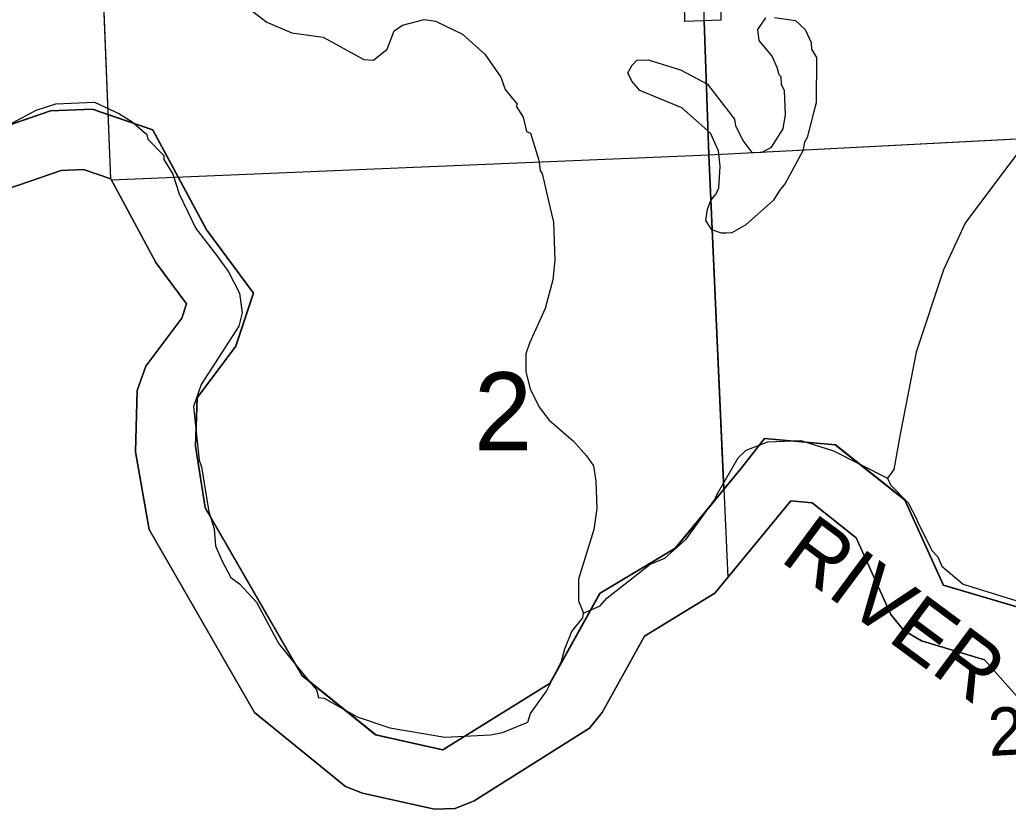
# Model space of a CAD drawing. Extents: x 128.7 to 185.5, y -21.4 to 12.6.
# Drawn here: x 156.23 to 157.877, y -14.035 to -12.718 of the extents above; entities that cross this region are included whole.
import ezdxf

# ---------------------------------------------------------------- set-up
doc = ezdxf.new("R2010")
doc.units = 0
for name, color, linetype in [('tdCoClipBndry', 7, 'Continuous'), ('tdCoCoBndry', 7, 'Continuous'), ('tdCoCoBndryPart', 7, 'Continuous'), ('tdCoHydroRiver', 7, 'Continuous'), ('tdCoHydroTxtLg', 7, 'Continuous'), ('tdCoSecRdTxt', 7, 'Continuous'), ('tdCoSecRteBand', 7, 'Continuous'), ('tdCoSectLine', 7, 'Continuous'), ('tdCoSectLinePart', 7, 'Continuous'), ('tdCoSectNmbr', 7, 'Continuous'), ('tdCoTwpBndry', 7, 'Continuous'), ('tdCoTwpBndryShd', 7, 'Continuous')]:
    doc.layers.add(name, color=color, linetype=linetype)

msp = doc.modelspace()

# ---------------------------------------------------------------- linework, layer by layer
at = {"layer": 'tdCoClipBndry'}
msp.add_lwpolyline([(157.9214, -13.8795), (157.8377, -13.7853), (157.7328, -13.754), (157.7035, -13.7363), (157.682, -13.7098), (157.6237, -13.5818), (157.5505, -13.5239), (157.5151, -13.5206), (157.3885, -13.6745), (157.2711, -13.7462), (157.2008, -13.873), (157.1797, -13.8993), (156.9873, -14.0205), (156.9554, -14.0333), (156.9211, -14.0346), (156.8011, -14.0079), (156.773, -13.9969), (156.6213, -13.8731), (156.4455, -13.5681), (156.4229, -13.4385), (156.4259, -13.3366), (156.4402, -13.2958), (156.5, -13.2156), (156.5079, -13.1918), (156.457, -13.1228), (156.3818, -12.9837), (156.336, -12.9681), (156.2993, -12.9695), (156.0482, -13.0555)], dxfattribs=at)
at = {"layer": 'tdCoCoBndry'}
for p, q in [((156.2812, -12.8702), (155.999, -12.9668)), ((155.999, -12.9668), (156.2812, -12.8702)), ((156.351, -12.8675), (156.2812, -12.8702)), ((156.2812, -12.8702), (156.351, -12.8675)), ((156.4516, -12.9018), (156.351, -12.8675)), ((156.351, -12.8675), (156.4516, -12.9018)), ((156.5417, -13.0692), (156.4516, -12.9018)), ((156.4516, -12.9018), (156.5417, -13.0692)), ((156.6196, -13.174), (156.5417, -13.0692)), ((156.5417, -13.0692), (156.6196, -13.174)), ((156.59, -13.2627), (156.6196, -13.174)), ((156.6196, -13.174), (156.59, -13.2627)), ((156.5255, -13.3486), (156.59, -13.2627)), ((156.59, -13.2627), (156.5255, -13.3486)), ((156.5228, -13.4292), (156.5255, -13.3486)), ((156.5255, -13.3486), (156.5228, -13.4292)), ((157.4714, -13.4162), (157.4337, -13.4646)), ((157.4337, -13.4646), (157.4714, -13.4162)), ((157.5896, -13.427), (157.4714, -13.4162)), ((157.4714, -13.4162), (157.5896, -13.427)), ((156.5388, -13.5314), (156.5228, -13.4292)), ((156.5228, -13.4292), (156.5388, -13.5314)), ((157.7051, -13.5185), (157.5896, -13.427)), ((157.5896, -13.427), (157.7051, -13.5185)), ((157.4337, -13.4646), (157.3235, -13.5989)), ((157.3235, -13.5989), (157.4337, -13.4646)), ((157.7695, -13.6609), (157.7051, -13.5185)), ((157.7051, -13.5185), (157.7695, -13.6609)), ((156.6999, -13.8109), (156.5388, -13.5314)), ((156.5388, -13.5314), (156.6999, -13.8109)), ((157.3235, -13.5989), (157.1972, -13.6741)), ((157.1972, -13.6741), (157.3235, -13.5989)), ((157.8938, -13.6975), (157.7695, -13.6609)), ((157.7695, -13.6609), (157.8938, -13.6975)), ((157.1972, -13.6741), (157.1138, -13.8245)), ((157.1138, -13.8245), (157.1972, -13.6741)), ((156.8235, -13.9104), (156.6999, -13.8109)), ((156.6999, -13.8109), (156.8235, -13.9104)), ((157.1138, -13.8245), (156.935, -13.9355)), ((156.935, -13.9355), (157.1138, -13.8245)), ((156.935, -13.9355), (156.8235, -13.9104)), ((156.8235, -13.9104), (156.935, -13.9355))]:
    msp.add_line(p, q, dxfattribs=at)
for points in [[(155.9986, -12.9668), (156.2808, -12.8702), (156.3507, -12.8675), (156.4512, -12.9018), (156.5414, -13.0692), (156.6192, -13.174), (156.5896, -13.2627), (156.5251, -13.3486), (156.5224, -13.4292), (156.5385, -13.5314), (156.6996, -13.8109), (156.8231, -13.9104), (156.9346, -13.9355), (157.1134, -13.8245), (157.1968, -13.6741), (157.3231, -13.5989), (157.4333, -13.4646), (157.471, -13.4162), (157.5892, -13.427), (157.7047, -13.5185), (157.7692, -13.6609), (157.8934, -13.6975)], [(157.8938, -13.6975), (157.7695, -13.6609), (157.7051, -13.5185), (157.5896, -13.427), (157.4714, -13.4162), (157.4337, -13.4646), (157.3235, -13.5989), (157.1972, -13.6741), (157.1138, -13.8245), (156.935, -13.9355), (156.8235, -13.9104), (156.6999, -13.8109), (156.5388, -13.5314), (156.5228, -13.4292), (156.5255, -13.3486), (156.59, -13.2627), (156.6196, -13.174), (156.5417, -13.0692), (156.4516, -12.9018), (156.351, -12.8675), (156.2812, -12.8702), (155.999, -12.9668)], [(157.8938, -13.6975), (157.7695, -13.6609), (157.7051, -13.5185), (157.5896, -13.427), (157.4714, -13.4162), (157.4337, -13.4646), (157.3235, -13.5989), (157.1972, -13.6741), (157.1138, -13.8245), (156.935, -13.9355), (156.8235, -13.9104), (156.6999, -13.8109), (156.5388, -13.5314), (156.5228, -13.4292), (156.5255, -13.3486), (156.59, -13.2627), (156.6196, -13.174), (156.5417, -13.0692), (156.4516, -12.9018), (156.351, -12.8675), (156.2812, -12.8702), (155.999, -12.9668)], [(156.0482, -13.0555), (156.2993, -12.9695), (156.336, -12.9681), (156.3818, -12.9837), (156.457, -13.1228), (156.5079, -13.1918), (156.5, -13.2156), (156.4402, -13.2958), (156.4259, -13.3366), (156.4229, -13.4385), (156.4455, -13.5681), (156.6213, -13.8731), (156.773, -13.9969), (156.8011, -14.0079), (156.9211, -14.0346), (156.9554, -14.0333), (156.9873, -14.0205), (157.1797, -13.8993), (157.2008, -13.873), (157.2711, -13.7462), (157.3885, -13.6745), (157.5151, -13.5206), (157.5505, -13.5239), (157.6237, -13.5818), (157.682, -13.7098), (157.7035, -13.7363), (157.7328, -13.754), (157.8377, -13.7853), (157.9214, -13.8795)]]:
    msp.add_lwpolyline(points, dxfattribs=at)
at = {"layer": 'tdCoCoBndryPart'}
msp.add_lwpolyline([(155.9986, -12.9668), (156.2808, -12.8702), (156.3507, -12.8675), (156.4512, -12.9018), (156.5414, -13.0692), (156.6192, -13.174), (156.5896, -13.2627), (156.5251, -13.3486), (156.5224, -13.4292), (156.5385, -13.5314), (156.6996, -13.8109), (156.8231, -13.9104), (156.9346, -13.9355), (157.1134, -13.8245), (157.1968, -13.6741), (157.3231, -13.5989), (157.4333, -13.4646), (157.471, -13.4162), (157.5892, -13.427), (157.7047, -13.5185), (157.7692, -13.6609), (157.8934, -13.6975)], dxfattribs=at)
at = {"layer": 'tdCoHydroRiver'}
for points in [[(156.616, -12.7028), (156.6419, -12.7224), (156.6836, -12.7399), (156.7359, -12.7475), (156.8036, -12.7845), (156.8194, -12.7855), (156.8424, -12.7673), (156.8539, -12.7369), (156.8678, -12.727), (156.9038, -12.7178), (156.9228, -12.7203), (156.9678, -12.7423), (157.0053, -12.7757), (157.0319, -12.8142), (157.039, -12.8345), (157.0588, -12.859), (157.0573, -12.8623), (157.069, -12.8808), (157.0746, -12.9043), (157.081, -12.9072), (157.0953, -12.9524), (157.0975, -12.9697), (157.1008, -12.9743), (157.1139, -13.0323), (157.1195, -13.0558), (157.1218, -13.1188), (157.1182, -13.1521), (157.1057, -13.1999), (157.0794, -13.2577), (157.0737, -13.2752), (157.0732, -13.3052), (157.0805, -13.3334), (157.0958, -13.3644), (157.1124, -13.3859), (157.1531, -13.4208), (157.1745, -13.4453), (157.1861, -13.4622), (157.1902, -13.4873), (157.1918, -13.533), (157.1868, -13.5679), (157.1613, -13.6509), (157.1611, -13.6873), (157.1697, -13.7075)], [(157.4074, -13.0739), (157.3995, -13.0741), (157.3836, -13.0684), (157.3735, -13.053), (157.376, -13.0339), (157.3818, -13.0195), (157.3909, -13.0082), (157.3953, -12.9985), (157.3971, -12.9622), (157.3946, -12.937), (157.381, -12.9075), (157.3337, -12.865), (157.2632, -12.8359), (157.25, -12.8206), (157.2432, -12.8067), (157.2506, -12.7938), (157.2582, -12.7856), (157.2771, -12.7849), (157.3314, -12.8019), (157.3764, -12.8256), (157.393, -12.8471), (157.4211, -12.884), (157.4231, -12.8949), (157.4282, -12.9058), (157.4351, -12.9198), (157.45, -12.9397), (157.4673, -12.9391), (157.4828, -12.9307), (157.5022, -12.9), (157.5061, -12.8762), (157.5047, -12.8368), (157.4996, -12.8259), (157.4991, -12.8133), (157.4959, -12.8102), (157.4923, -12.7977), (157.4837, -12.7791), (157.4622, -12.753), (157.46, -12.7342), (157.4735, -12.7148)], [(157.4877, -12.7142), (157.5226, -12.7193), (157.5389, -12.7345), (157.5492, -12.7562), (157.5496, -12.7673), (157.558, -12.7812), (157.5575, -12.857), (157.5533, -12.8713), (157.5422, -12.9143), (157.5378, -12.9224), (157.5351, -12.9367), (157.5055, -12.9914), (157.4964, -13.0028), (157.486, -13.019), (157.4401, -13.0601), (157.4169, -13.0735), (157.4074, -13.0739)], [(158.1142, -12.7092), (158.0713, -12.7454), (158.053, -12.7635), (158.036, -12.7735), (157.9523, -12.8618), (157.8062, -13.0564), (157.7695, -13.1351), (157.7239, -13.2725), (157.6973, -13.4092), (157.6867, -13.468), (157.6762, -13.4825)], [(156.1179, -12.9432), (156.2573, -12.8688), (156.29, -12.8582), (156.3547, -12.8558), (156.3964, -12.8749), (156.4174, -12.8883), (156.4418, -12.9095), (156.4437, -12.9174), (156.4699, -12.9448), (156.4702, -12.9511), (156.4852, -12.9759), (156.4959, -13.0086), (156.5232, -13.0661), (156.5579, -13.1106), (156.5779, -13.1383), (156.5965, -13.1739), (156.6009, -13.2069), (156.5953, -13.2292), (156.5325, -13.3262), (156.5196, -13.3629), (156.5291, -13.4526), (156.5327, -13.4635), (156.5449, -13.5388), (156.5538, -13.5669), (156.5563, -13.5952), (156.5667, -13.6201), (156.5819, -13.648), (156.5965, -13.6585), (156.6244, -13.6891), (156.6616, -13.7588), (156.7013, -13.8079), (156.7244, -13.8355), (156.728, -13.848), (156.7375, -13.8492), (156.7923, -13.8804), (156.8466, -13.899), (156.9387, -13.9146), (157.0144, -13.9103), (157.0347, -13.9065), (157.0767, -13.8892), (157.081, -13.8748), (157.108, -13.8375), (157.1331, -13.7877), (157.1387, -13.767), (157.1502, -13.7382), (157.1684, -13.7154), (157.1697, -13.7075), (157.1976, -13.6954), (157.2082, -13.6824), (157.2804, -13.6261), (157.3053, -13.6158), (157.3405, -13.5845), (157.3886, -13.5181), (157.3915, -13.5101), (157.4272, -13.4488), (157.4409, -13.4357), (157.4767, -13.4218), (157.5319, -13.4198), (157.5862, -13.4368), (157.6762, -13.4825), (157.6813, -13.4934), (157.7108, -13.5239), (157.7244, -13.5503), (157.7262, -13.5549), (157.75, -13.603), (157.7598, -13.6137), (157.7667, -13.6293), (157.8025, -13.6595), (157.8903, -13.6864)]]:
    msp.add_lwpolyline(points, dxfattribs=at)
at = {"layer": 'tdCoSecRteBand'}
msp.add_lwpolyline([(157.3976, -12.6888), (157.3987, -12.7188), (157.3387, -12.721), (157.3376, -12.6911)], dxfattribs=at)
at = {"layer": 'tdCoSectLine'}
for points in [[(157.3424, -11.9378), (157.3787, -12.9432)], [(156.3412, -11.9779), (156.3814, -12.9836)], [(157.3787, -12.9432), (158.3825, -12.8911)], [(156.3826, -12.9851), (157.3787, -12.9432)], [(157.3787, -12.9432), (157.41, -13.6484)]]:
    msp.add_lwpolyline(points, dxfattribs=at)
at = {"layer": 'tdCoSectLinePart'}
for points in [[(156.3626, -12.5138), (156.3814, -12.9836)], [(157.3707, -12.7203), (157.3787, -12.9432)], [(157.3787, -12.9432), (158.3528, -12.8927)], [(156.3826, -12.9851), (157.3787, -12.9432)], [(157.3787, -12.9432), (157.41, -13.6484)]]:
    msp.add_lwpolyline(points, dxfattribs=at)
at = {"layer": 'tdCoTwpBndry'}
msp.add_lwpolyline([(157.4035, -13.502), (157.3787, -12.9432), (157.3706, -12.7198)], dxfattribs=at)
at = {"layer": 'tdCoTwpBndryShd'}
for points in [[(157.7372, 5.1315), (157.7796, 4.1166), (157.8244, 3.1167), (157.8671, 2.1048), (157.9089, 1.1243), (157.9561, 0.1126), (157.999, -0.8918), (158.0323, -1.8928), (158.0641, -2.8906), (158.09, -3.8899), (158.1261, -4.8909), (158.1526, -5.8934), (158.186, -6.8922), (158.2224, -7.8865), (158.2596, -8.8901), (157.2411, -8.925), (157.2808, -9.9203), (157.3135, -10.9318), (157.3424, -11.9378), (157.3787, -12.9432), (157.4034, -13.501)], [(155.9986, -12.9668), (156.2808, -12.8702), (156.3507, -12.8675), (156.4512, -12.9018), (156.5414, -13.0692), (156.6192, -13.174), (156.5896, -13.2627), (156.5251, -13.3486), (156.5224, -13.4292), (156.5385, -13.5314), (156.6996, -13.8109), (156.8231, -13.9104), (156.9346, -13.9355), (157.1134, -13.8245), (157.1968, -13.6741), (157.3231, -13.5989), (157.4333, -13.4646), (157.471, -13.4162), (157.5892, -13.427), (157.7047, -13.5185), (157.7692, -13.6609), (157.8934, -13.6975)]]:
    msp.add_lwpolyline(points, dxfattribs=at)

# ---------------------------------------------------------------- texts
at = {"layer": 'tdCoHydroTxtLg'}
msp.add_text('RIVER', height=0.1, rotation=323.4314, dxfattribs=at).set_placement((157.495, -13.6192))
at = {"layer": 'tdCoSecRdTxt'}
msp.add_text('291ST ST', height=0.08, rotation=3.1181, dxfattribs=at).set_placement((157.8459, -13.946))
at = {"layer": 'tdCoSectNmbr'}
msp.add_text('2', height=0.13, rotation=0.1179, dxfattribs=at).set_placement((156.9872, -13.4361))

doc.saveas('drawing.dxf')
